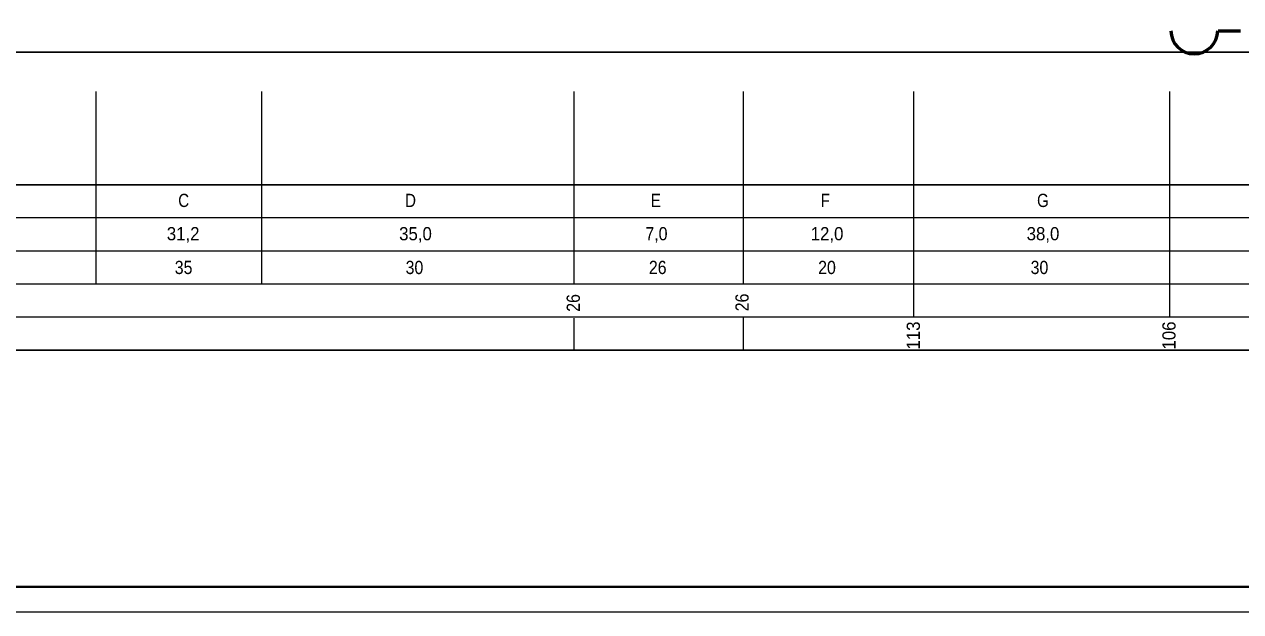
# Model space of a CAD drawing. Extents: x 8426.2 to 8495.4, y 19933.5 to 19963.2.
# Drawn here: x 8443.58 to 8468.08, y 19933.55 to 19945.38 of the extents above; entities that cross this region are included whole.
import ezdxf

# ---------------------------------------------------------------- set-up
doc = ezdxf.new("R2010")
doc.units = 0
doc.header["$LTSCALE"] = 0.11
for name, color, linetype, lineweight in [('1', 7, 'Continuous', 35), ('2', 7, 'Continuous', 13), ('3', 7, 'Continuous', 25)]:
    doc.layers.add(name, color=color, linetype=linetype, lineweight=lineweight)

msp = doc.modelspace()

# ---------------------------------------------------------------- linework, layer by layer
at = {"layer": '1', "lineweight": 13}
msp.add_lwpolyline([(8426.17, 19933.55), (8495.44, 19933.55), (8495.44, 19963.25), (8426.17, 19963.25)], close=True, dxfattribs=at)
at = {"layer": '1', "lineweight": 40}
msp.add_lwpolyline([(8428.67, 19934.05), (8494.94, 19934.05), (8494.94, 19962.75)], dxfattribs=at)
at = {"layer": '2', "lineweight": 53}
msp.add_line((8467.63, 19945.25), (8468.08, 19945.25), dxfattribs=at)
msp.add_arc((8467.147, 19945.256), 0.472, 180.7304, 359.2696, dxfattribs=at)
msp.add_arc((8467.147, 19945.256), 0.472, 180.7304, 359.2696, dxfattribs=at)
msp.add_arc((8467.147, 19945.256), 0.472, 180.7304, 359.2696, dxfattribs=at)
at = {"layer": '3'}
for p, q in [((8431.27, 19944.82), (8493.73, 19944.82)), ((8432.23, 19942.15), (8490.75, 19942.15)), ((8432.23, 19938.82), (8490.75, 19938.82))]:
    msp.add_line(p, q, dxfattribs=at)
at = {"layer": '3', "lineweight": 13}
for p, q in [((8445.02, 19944.03), (8445.02, 19940.15)), ((8448.36, 19944.03), (8448.36, 19940.15)), ((8454.65, 19944.03), (8454.65, 19940.17)), ((8458.06, 19944.03), (8458.06, 19940.14)), ((8461.49, 19944.03), (8461.49, 19939.49)), ((8466.65, 19944.03), (8466.65, 19939.49)), ((8432.23, 19941.49), (8490.75, 19941.49)), ((8432.23, 19940.82), (8490.75, 19940.82)), ((8432.23, 19940.15), (8490.75, 19940.15)), ((8433.47, 19940.15), (8490.75, 19940.15)), ((8432.23, 19939.49), (8490.75, 19939.49)), ((8454.65, 19939.46), (8454.65, 19938.82)), ((8458.06, 19939.48), (8458.06, 19938.82))]:
    msp.add_line(p, q, dxfattribs=at)

# ---------------------------------------------------------------- texts
at = {"layer": '3'}
for s, height, width, p in [('C', 0.267, 0.85, (8446.68, 19941.7)), ('D', 0.267, 0.85, (8451.25, 19941.7)), ('E', 0.267, 0.85, (8456.2, 19941.7)), ('F', 0.267, 0.85, (8459.62, 19941.7)), ('G', 0.267, 0.85, (8463.98, 19941.7)), ('31,2', 0.2665, 0.95, (8446.45, 19941.03)), ('35,0', 0.2665, 0.95, (8451.13, 19941.03)), ('7,0', 0.2665, 0.9, (8456.09, 19941.03)), ('12,0', 0.2665, 0.95, (8459.42, 19941.03)), ('38,0', 0.2665, 0.95, (8463.77, 19941.03)), ('35', 0.2665, 0.9, (8446.61, 19940.35)), ('30', 0.2665, 0.9, (8451.26, 19940.35)), ('26', 0.2665, 0.9, (8456.16, 19940.35)), ('20', 0.2665, 0.9, (8459.57, 19940.35)), ('30', 0.2665, 0.9, (8463.85, 19940.35))]:
    msp.add_text(s, height=height, dxfattribs=dict(at, width=width)).set_placement(p)
for s, width, p in [('26', 0.9, (8454.77, 19939.59)), ('26', 0.9, (8458.17, 19939.6)), ('113', 0.95, (8461.62, 19938.83)), ('106', 0.95, (8466.77, 19938.83))]:
    msp.add_text(s, height=0.2665, rotation=90, dxfattribs=dict(at, width=width)).set_placement(p)

doc.saveas('drawing.dxf')
